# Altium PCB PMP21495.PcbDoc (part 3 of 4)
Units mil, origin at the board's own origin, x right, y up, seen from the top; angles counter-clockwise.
Board outline 10700 x 5800 mil, 6 copper layers (Top Layer, Signal Layer 3, Signal Layer 1, Signal Layer 2, Signal Layer 4, Bottom Layer), stack 66 mil thick; 305 components, 138 nets, 864 pads, 367 vias.
Unrouted connection lines stored in the file: 2.
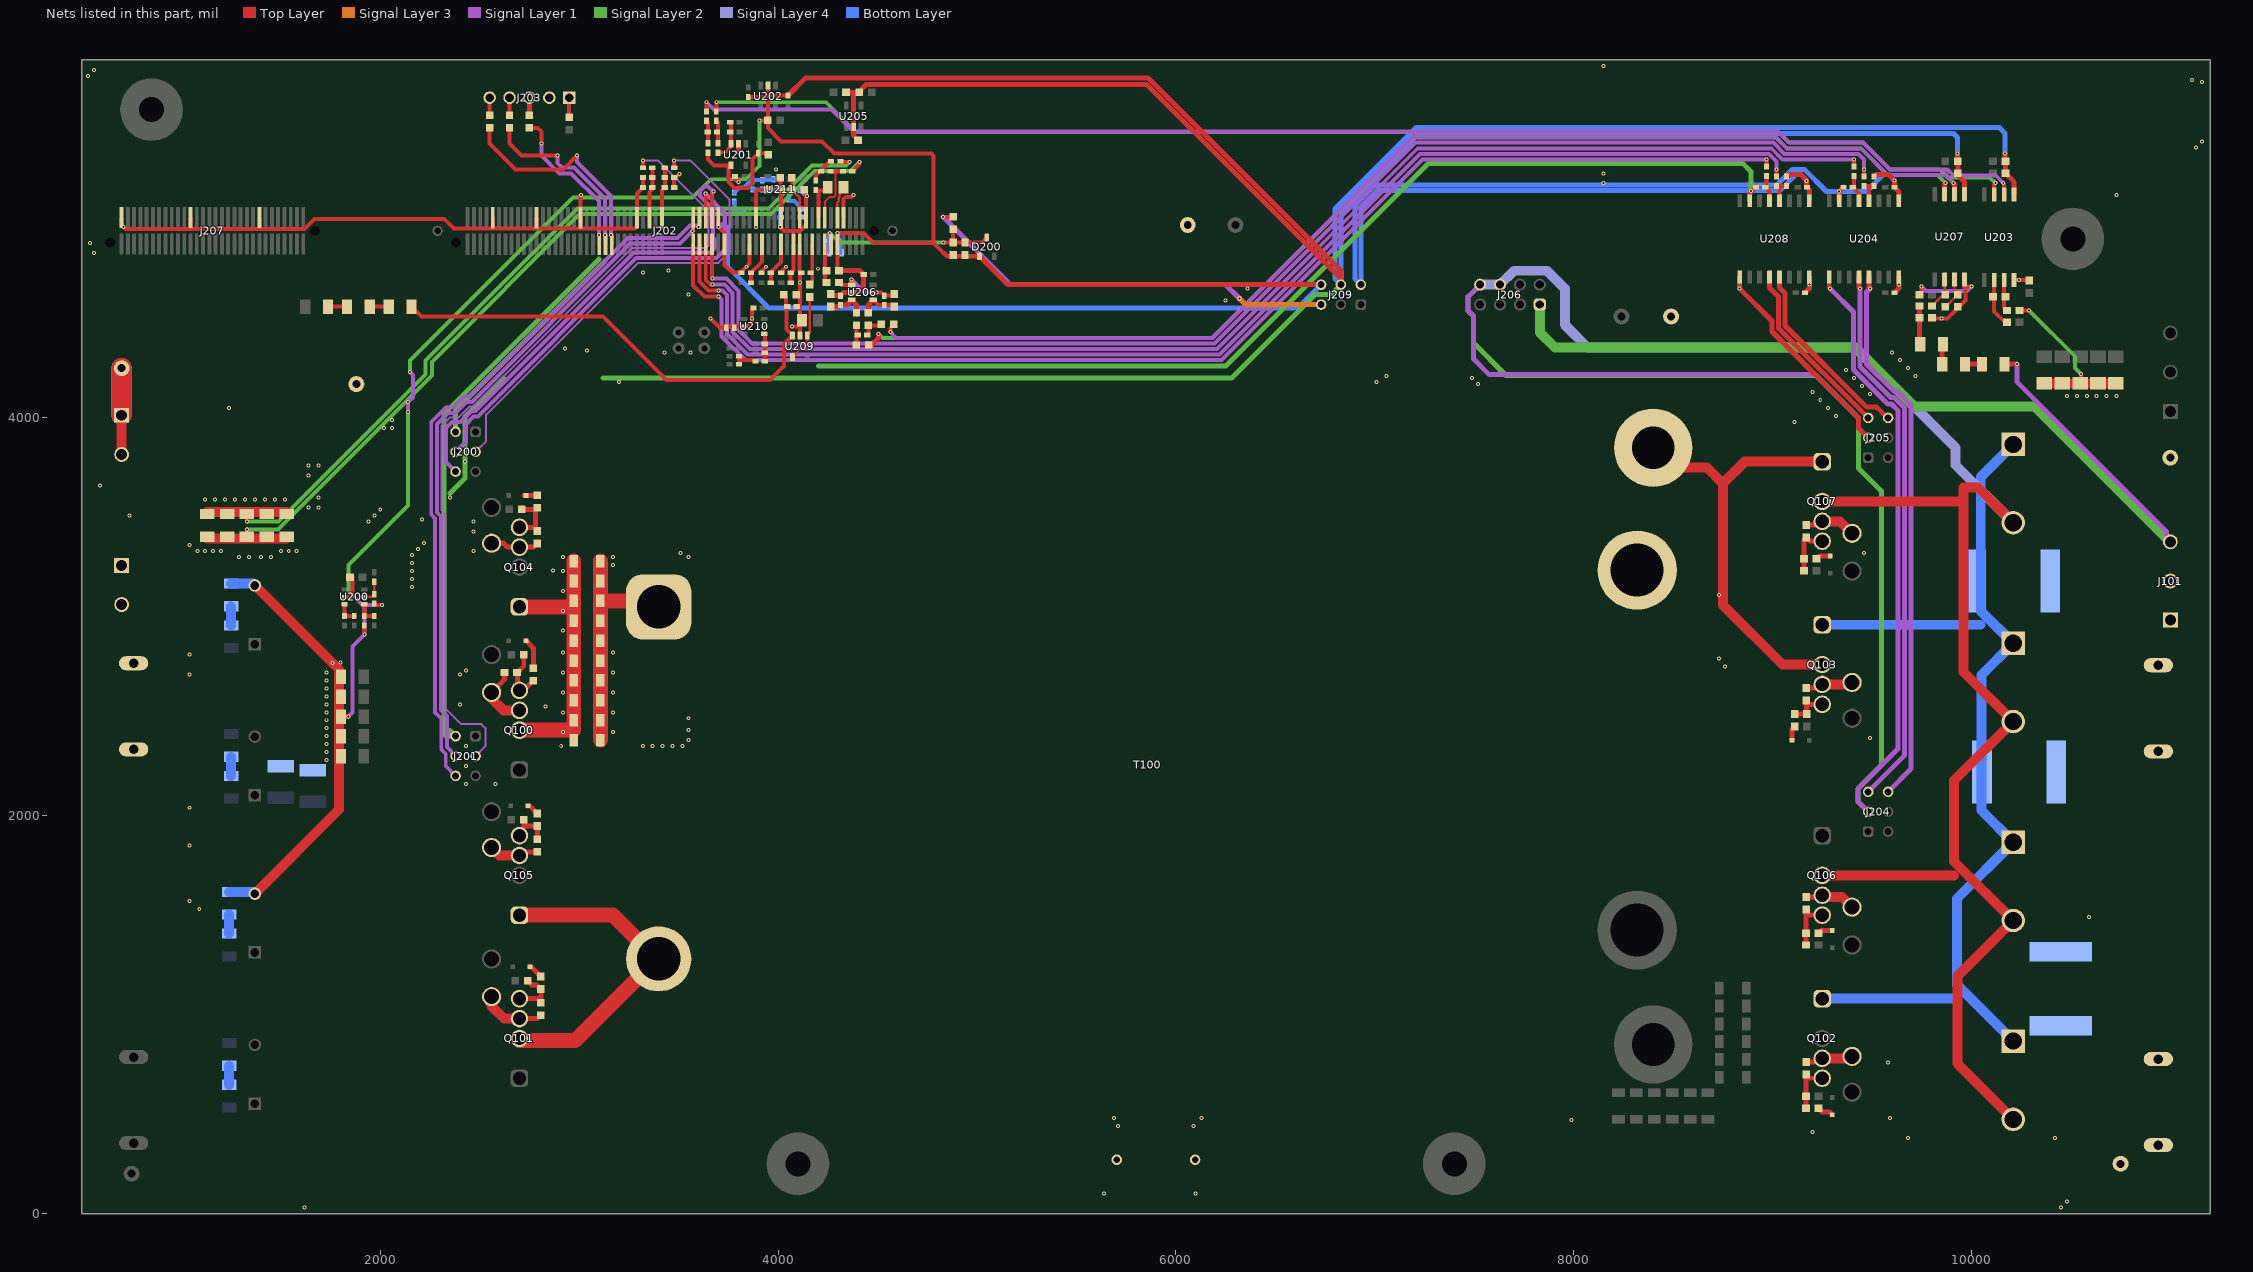
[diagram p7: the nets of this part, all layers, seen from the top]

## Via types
v1: diameter 20, hole 10, Top Layer to Bottom Layer, 367 vias

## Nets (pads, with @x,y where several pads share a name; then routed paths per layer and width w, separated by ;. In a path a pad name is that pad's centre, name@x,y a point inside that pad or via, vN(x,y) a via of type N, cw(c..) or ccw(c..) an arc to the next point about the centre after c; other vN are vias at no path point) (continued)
NetC103_1: C103.1 C104.1 C106.1 C107.1 C132.1 C133.1 C142.1 Q102.1 Q103.1 TP101.1 XF102.1 XF102.2 | length 4976
  Bottom Layer w50: Q102.1@9250,1080 9926.85,1080 ; Q103.1@9250,2960 10046.85,2960 ; C107.1@10210,866.85 9926.85,1150 9926.85,1583.7 C106.1@10210,1866.85 10050,2026.85 10050,2706.85 C104.1@10210,2866.85 10046.85,3030 10046.85,3703.7 C103.1@10210,3866.85
NetC122_1: C122.1 C124.1 C126.1 C128.1 C134.1 C136.1 C138.1 C140.1 C146.1 C148.1 T100.1 | length 1153.1
  Top Layer w75: C128.1@3106.93,2380 C134.1@3106.93,2480 C126.1@3106.93,2580 C122.1@3106.93,2680 C124.1@3106.93,2780 C146.1@3106.93,2880 C148.1@3106.93,2980 C140.1@3106.93,3080 ; C138.1@3106.93,3280 C136.1@3106.93,3180 C140.1@3106.93,3080 ; T100.1@3360,3080 C140.1@3106.93,3080
  other v1: 3320,2350 3370,2350 3420,2350 3470,2350 3520,2350 3550,2380 3170,2420 3550,2430 3550,2490 3170,2520 3170,2620 3170,2720 3170,2820 3170,3260 3170,3300 3550,3300 3510,3320
NetC122_2: C122.2 C124.2 C126.2 C128.2 C134.2 C136.2 C138.2 C140.2 C146.2 C148.2 Q100.2 Q104.1 | length 1346.1
  Top Layer w75: Q100.2@2710,2430 2973.07,2430 C134.2@2973.07,2480 C126.2@2973.07,2580 C122.2@2973.07,2680 C124.2@2973.07,2780 C146.2@2973.07,2880 C148.2@2973.07,2980 C140.2@2973.07,3080 C136.2@2973.07,3180 C138.2@2973.07,3280 ; Q104.1@2710,3050 2943.07,3050
  other v1: 2910,2350 2920,2420 2920,2520 2830,2550 2920,2620 2920,2720 2920,2820 2920,2930 2920,3030 2920,3130 2920,3230 2868.84,3232.2 2920,3300
NetC200_1: C200.1 R203.2 R211.1 | length 132.7
  Top Layer w20: R211.1@4190,5193.62 4190,5221.65 4258.35,5290 R203.2@4266.38,5290
NetC200_2: C200.2 J202.13 R207.2 | length 331.2
  Top Layer w10: J202.13@4235,5007.05 4235,5087.22 4257.78,5110 4279.55,5110 4290,5120.45 4290,5240
  Top Layer w20: C200.2@4263.62,5240 4290,5240 R207.2@4326.38,5240
NetC202_2: C202.2 J202.14 R209.1 | length 184.3
  Top Layer w20: R209.1@4235,4688.9 J202.14@4235,4873.19
NetC203_1: C203.1 R210.1 R214.2 U209.3 | length 2451.1
  Top Layer w20: R210.1@2157.09,4560 2207.09,4510 3120,4510 3440,4190 3960,4190 4030,4260 4030,4371.54 U209.3@4072.6,4414.13 4042.13,4444.61 4042.13,4564.25 4040,4566.38 4040,4608.5 R214.2@4028.5,4620
NetC204_1: C204.1 J202.21 R212.2 | length 217.7
  Top Layer w12: R212.2@4068.5,5207.13 C204.1@4068.5,5147.13 4110,5105.63 4110,5008.03 J202.21@4109.02,5007.05
NetC205_1: C205.1 J202.27 R218.1 | length 197
  Top Layer w12: C205.1@4008.5,5147.13 C205.1@4011.5,5147.13
  Top Layer w20: C205.1@4011.5,5150.12 R218.1@4011.5,5207.13 ; J202.27@4014.53,5007.05 C205.1@4014.53,5144.09
NetC206_1: C206.1 J202.57 R221.1 R223.2 | length 257.4
  Top Layer w19.68: J202.57@3416.1,5007.05 3416.1,5143.66
  Top Layer w20: 3416.1,5143.66 C206.1@3430.79,5158.35 R221.1@3430.79,5258.35
NetC207_1: C207.1 J202.61 R222.1 R224.2 | length 257.5
  Top Layer w19.68: J202.61@3353.11,5007.05 3353.11,5135.39
  Top Layer w20: 3353.11,5135.39 3368.03,5150.31 C207.1@3368.03,5158.35 R222.1@3368.03,5258.35
NetC208_2: C208.2 R225.1 R232.2 U201.4 | length 604
  Top Layer w20: R232.2@3648.35,5333.5 3648.35,5298.78 3678.87,5268.25 3761.67,5268.25 3750,5256.58 3750,5187.13 3780.37,5156.75 3812.58,5156.75 3812.96,5157.13 3850,5157.13 3871.81,5178.94 3871.81,5301.5 C208.2@3900.95,5330.64 R225.1@3950.95,5330.64
NetC215_1: C215.1 R230.2 U203.2 | length 245
  Top Layer w20: U203.2@10114.49,4693.46 10114.49,4535.51 10170,4480 R230.2@10178.5,4480
NetC215_2: C215.2 R235.2 U203.3 | length 159.3
  Top Layer w20: U203.3@10164.49,4693.46 10164.49,4554.02 R235.2@10178.5,4540
NetC216_1: C216.1 R231.2 R232.1 | length 116.2
  Top Layer w20: R231.2@3640,5493.5 3648.35,5485.16 R232.1@3648.35,5380.75
NetC216_2: C216.2 R233.2 R234.1 | length 116.2
  Top Layer w20: R233.2@3690,5493.5 3698.35,5485.16 R234.1@3698.35,5380.75
NetC217_1: C217.1 R234.2 R236.2 U201.3 | length 196.9
  Top Layer w19.68: R234.2@3698.35,5333.5 3733.5,5333.5 3763.54,5363.54 U201.3@3763.54,5378.39 C217.1@3763.54,5482.83
NetC221_2: C221.2 R238.1 R243.2 U206.4 | length 199.5
  Top Layer w20: U206.4@4478.54,4593.58 4504.76,4567.36 R238.1@4584.41,4567.36
  Top Layer w25: R243.2@4454.41,4520.85 4454.41,4569.45 U206.4@4478.54,4593.58
NetC228_1: C228.1 R241.2 U207.2 | length 161.1
  Top Layer w12: R241.2@9801.5,4562.8 9802.3,4562.8 9835.06,4595.55 9835.06,4596.36 9862.2,4623.5 9865,4623.5 U207.2@9865,4695.43
NetC228_2: C228.2 R247.2 U207.3 | length 170.1
  Top Layer w12: R247.2@9868.5,4560 9871.5,4560 C228.2@9931.5,4620 9915,4636.5 U207.3@9915,4695.43
NetC229_1: C229.1 R242.2 R243.1 | length 108
  Top Layer w20: C229.1@4454.41,4423.6 R243.1@4454.41,4465.73 4514.23,4465.73 R242.2@4518.5,4470
NetC229_2: C229.2 R244.2 R245.1 | length 100.5
  Top Layer w20: R244.2@4394.41,4373.11 R245.1@4394.41,4473.6
NetC232_1: C232.1 R245.2 R248.2 U206.3 | length 202.7
  Top Layer w25: R248.2@4264.41,4559.49 4306.54,4559.49 C232.1@4314.41,4567.36 4344.06,4567.36 U206.3@4370.28,4593.58 4394.41,4569.45 R245.2@4394.41,4520.85
NetC234_1: C234.1 R219.2 U204.5 | length 140.1
  Top Layer w20: R219.2@9410,5216.38 9410,5166.38 C234.1@9403.62,5160 9435,5128.62 U204.5@9435,5091.93
NetC235_1: C235.1 R200.2 U204.4 | length 124.4
  Top Layer w20: R200.2@9460,5166.38 C235.1@9510,5166.38 ; U204.4@9485,5091.93 9485,5166.38
NetC236_1: C236.1 R220.2 U208.5 | length 135.9
  Top Layer w20: R220.2@8970,5216.38 8970,5166.38 C236.1@8963.62,5160 8985,5138.62 U208.5@8985,5091.93
NetC237_1: C237.1 R201.2 U208.4 | length 119.4
  Top Layer w20: R201.2@9020,5166.38 C237.1@9070,5166.38 ; U208.4@9035,5091.93 9035,5161.38
NetC238_1: C238.1 C239.1 C240.1 D200.3 J202.12 R226.1 R227.2 | length 1040.9
  Top Layer w20: v1(4260,4930) 4266.5,4923.5 J202.12@4266.5,4873.19 ; v1(4831.5,4881.5) R227.2@4880,4881.5 ; R226.1@4880,4948.5 R227.2@4880,4881.5 ; D200.3@5050,4907.24 5024.25,4881.5 R227.2@4880,4881.5
  Signal Layer 2 w20: v1(4260,4930) 4308.5,4881.5 v1(4831.5,4881.5)
  Bottom Layer w20: C240.1@4256.38,4837.87 C239.1@4256.38,4890 4256.38,4926.38 v1(4260,4930)
NetC241_1: C241.1 J202.18 R228.1 | length 206.7
  Top Layer w20: R228.1@4160,4671.5 4172.01,4683.5 J202.18@4172.01,4873.19
NetC242_1: C242.1 J202.24 R229.2 | length 198.9
  Top Layer w20: R229.2@4063.62,4680 C242.1@4063.62,4730 4077.52,4743.9 J202.24@4077.52,4873.19
NetC244_1: C244.1 J202.34 R253.1 | length 217.2
  Top Layer w20: R253.1@3863.62,4680 C244.1@3863.62,4730 3864.1,4730 3882.76,4748.66 3882.76,4749.21 3893.23,4759.69 3893.78,4759.69 3920.04,4785.94 J202.34@3920.04,4873.19
NetC245_1: C245.1 J202.28 R254.1 | length 214.3
  Top Layer w20: R254.1@3963.62,4680 C245.1@3963.62,4730 3963.62,4733.62 4014.53,4784.53 J202.28@4014.53,4873.19
NetC246_2: C246.2 R255.1 R258.1 U210.4 | length 129.2
  Top Layer w20: R258.1@3933.62,4290 C246.2@3933.62,4327.72 U210.4@3933.62,4419.17
NetC248_1: C248.1 R257.2 R258.2 | length 122.8
  Top Layer w20: R257.2@3803.62,4270 3803.62,4290 ; C248.1@3803.62,4310 3803.62,4290 ; R258.2@3886.38,4290 3803.62,4290
NetC250_1: C250.1 R260.2 R264.2 U211.1 | length 294.1
  Bottom Layer w20: C250.1@3873.37,5148.27 4031.73,5148.27 4051.85,5128.15 U211.1@4051.85,5099.8 4061.65,5090 4082.01,5090 R264.2@4113.62,5058.38
NetC250_2: C250.2 R260.1 R263.1 U211.4 | length 216.8
  Bottom Layer w20: R263.1@3780,5133.62 3805.63,5159.25 3829.25,5159.25 C250.2@3865.51,5195.51 ; C250.2@3873.37,5195.51 3972.36,5195.51 U211.4@3977.05,5200.2
NetC252_1: C252.1 R262.2 R263.2 | length 102.8
  Bottom Layer w20: R263.2@3780,5086.38 R262.2@3780,5033.62 C252.1@3830,5033.62
NetD100_2: D100.2 R122.1 | length 153.7
  Top Layer w25: D100.2@2733.31,2880 2770,2843.31 R122.1@2770,2741.5
NetD101_2: D101.2 R123.1 | length 74
  Top Layer w25: D101.2@2753.31,1240 2758.68,1240 R123.1@2807.18,1191.5
NetD102_2: D102.2 R124.1 | length 82.2
  Top Layer w25: R124.1@9231.5,529.67 9251.16,510 9286.69,510 D102.2@9300,496.69
NetD103_2: D103.2 R125.1 | length 74
  Top Layer w25: D103.2@9098.05,2380 9098.05,2435.2 R125.1@9111.36,2448.5
NetD104_2: D104.2 R134.1 | length 65.2
  Top Layer w25: D104.2@2723.31,3610 R134.1@2788.5,3610
NetD105_2: D105.2 R135.1 | length 62.6
  Top Layer w25: D105.2@2743.31,2050 2751.5,2050 R135.1@2790,2011.5
NetD106_2: D106.2 R136.1 | length 74
  Top Layer w25: R136.1@9231.5,1410 9244.8,1423.31 D106.2@9300,1423.31
NetD107_2: D107.2 R137.1 | length 74.4
  Top Layer w25: R137.1@9221.5,3291.46 9235.83,3305.79 D107.2@9290,3305.79
NetJ105_1: J105.1 Q103.2 Q107.1 T100.8 | length 2163
  Top Layer w50: J105.1@8400,3750 8670,3750 8750,3670 ; Q103.2@9250,2760 9050,2760 8750,3060 8750,3670 ; Q107.1@9250,3780 8860,3780 8750,3670
  other v1: 8760,2750 8730,2790 8730,3110 9110,3980
NetJ202_15: J202.15 R206.1 R211.2 | length 166.5
  Top Layer w19.68: R211.2@4200,5143.5 R206.1@4233.5,5143.5 ; J202.15@4203.5,5007.05 4203.5,5140
NetJ203_1: J203.1 R252.1 | length 98.5
  Top Layer w20: R252.1@2950,5511.5 J203.1@2950,5610
NetJ203_3: J203.3 R249.2 | length 88.5
  Top Layer w25: R249.2@2750,5521.5 J203.3@2750,5610
NetJ203_4: J203.4 R251.2 | length 88.5
  Top Layer w20: R251.2@2650,5521.5 J203.4@2650,5610
NetJ203_5: J203.5 R250.2 | length 88.5
  Top Layer w20: R250.2@2550,5521.5 J203.5@2550,5610
NetJ204_5: J204.5 U204.12 | length 2768.6
  Top Layer w25: U204.12@9435,4708.07 9435,4655 v1(9440,4650)
  Signal Layer 1 w25: v1(9440,4650) 9440,4256.49 9593.62,4102.87 9612.02,4102.87 9662.87,4052.02 9662.87,2301.87 J204.5@9481,2120
NetJ204_6: J204.6 U204.13 | length 2747.9
  Top Layer w25: U204.13@9485,4708.07 9485,4655 v1(9490,4650)
  Signal Layer 1 w25: v1(9490,4650) 9472.87,4632.87 9472.87,4270.11 9607.23,4135.75 9625.64,4135.75 9695.75,4065.64 9695.75,2234.75 J204.6@9581,2120
NetJ205_5: J205.5 U208.12 | length 913.5
  Top Layer w25: U208.12@8985,4708.07 8985,4655 9030,4610 9030,4451 J205.5@9481,4000
NetJ205_6: J205.6 U208.13 | length 965.6
  Top Layer w25: U208.13@9035,4708.07 9035,4655 9062.87,4627.13 9062.87,4464.62 9473.73,4053.76 9523.73,4053.76 9577.49,4000 J205.6@9581,4000
NetQ100_4: Q100.4 R118.2 R122.2 R126.2 | length 287.3
  Top Layer w25: R118.2@2721.5,2810 2721.5,2751.5 2690,2720 2690,2640 Q100.4@2700,2630 2721.5,2630 R122.2@2770,2678.5
NetQ101_2: Q101.2 Q105.1 T100.3 | length 1641
  Top Layer w75: Q101.2@2700,870 2980,870 3390,1280 3170,1500 Q105.1@2700,1500
NetQ101_4: Q101.4 R119.2 R123.2 R127.2 | length 238.6
  Top Layer w25: Q101.4@2700,1080 2807.18,1080 R123.2@2807.18,1128.5 2785.69,1150 2761.5,1150 R119.2@2741.5,1170
NetQ102_4: Q102.4 R120.2 R124.2 R128.2 | length 239.5
  Top Layer w25: R124.2@9168.5,529.67 R120.2@9168.5,589.67 9168.5,697.01 R128.2@9170,698.5 ; R128.2@9179.98,680 Q102.4@9250,680
NetQ103_4: Q103.4 R121.2 R125.2 R129.2 | length 197.6
  Top Layer w25: R125.2@9111.36,2511.5 R121.2@9171.36,2511.5 9170,2512.85 R129.2@9170,2578.5 ; R129.2@9179.98,2560 Q103.4@9250,2560
NetQ104_4: Q104.4 R130.2 R134.2 R138.2 | length 241.5
  Top Layer w25: Q104.4@2700,3450 R138.2@2771.5,3450 ; R130.2@2711.5,3540 2781.5,3540 R138.2@2781.5,3440
NetQ105_4: Q105.4 R131.2 R135.2 R139.2 | length 190.9
  Top Layer w25: Q105.4@2721.5,1921.5 R131.2@2721.5,1980 ; 2722.99,1948.5 R135.2@2790,1948.5 R139.2@2790,1883.11
NetQ106_4: Q106.4 R132.2 R136.2 R140.2 | length 257.5
  Top Layer w25: R132.2@9168.5,1350 R136.2@9168.5,1410 R140.2@9168.5,1527.01 ; 9169.53,1500 Q106.4@9250,1500
NetQ107_4: Q107.4 R133.2 R137.2 R141.2 | length 259.5
  Top Layer w25: R133.2@9158.5,3231.46 R137.2@9158.5,3291.46 9158.5,3387.01 R141.2@9170,3398.5 9188.5,3380 Q107.4@9250,3380
NetR100_1: R100.1 R105.2 | length 95.8
  Bottom Layer w50: R100.1@1240,647.09 R105.2@1240,742.91
NetR101_1: R101.1 R106.2 | length 95.8
  Bottom Layer w50: R101.1@1250,2200.18 R106.2@1250,2296
NetR110_1: R110.1 R114.2 | length 95.8
  Bottom Layer w50: R110.1@1240,1407.09 R114.2@1240,1502.91
NetR111_1: R111.1 R115.2 | length 95.8
  Bottom Layer w50: R111.1@1250,2957.09 R115.2@1250,3052.91
NetR202_1: R202.1 R205.2 | length 95.8
  Top Layer w20: R202.1@1737.09,4560 R205.2@1832.91,4560
NetR204_1: R204.1 R216.2 U200.4 | length 108.8
  Top Layer w20: R216.2@1920,3003.62 R204.1@1970,3003.62 ; R216.2@1920.2,3003.82 U200.4@1920.2,3062.6
NetR205_1: R205.1 R210.2 | length 95.8
  Top Layer w20: R205.1@1947.09,4560 R210.2@2042.91,4560
NetR208_1: R208.1 R217.2 U200.5 | length 118.2
  Top Layer w12: U200.5@1920.2,3100 1956.38,3100 R217.2@1970,3113.62 R208.1@1970,3176.38
NetR213_1: R213.1 R215.2 U200.3 | length 108.8
  Top Layer w20: U200.3@1819.8,3062.6 1819.8,3003.82 R215.2@1869.8,3003.82
NetR231_1: R231.1 U203.6 | length 6794.3
  Top Layer w20: R231.1@3640,5540.75 v1(3640,5587.13) ; v1(10160,5180) 10164.49,5175.51 U203.6@10164.49,5122.6
  Signal Layer 1 w20: v1(3640,5587.13) 3677.13,5550 4269.37,5550 4380,5439.37 9028.31,5439.37 9084.06,5383.62 9455.22,5383.62 9590.22,5248.62 9880.8,5248.62 9909.42,5220 10120,5220 v1(10160,5180)
NetR233_1: R233.1 U203.7 | length 6704.7
  Top Layer w20: R233.1@3690,5540.75 v1(3690,5587.13) ; U203.7@10114.49,5122.6 10114.49,5174.49 v1(10120,5180)
  Signal Layer 2 w20: v1(3690,5587.13) 4240.75,5587.13 4390,5437.87 9029.8,5437.87 9083.84,5383.84 9455,5383.84 9590.22,5248.62 9840.8,5248.62 9879.71,5209.71 10090.29,5209.71 v1(10120,5180)
NetR237_1: R237.1 R239.2 | length 85.8
  Top Layer w25: R239.2@9967.09,4270 R237.1@10052.91,4270
NetR239_1: R239.1 R240.2 | length 95.8
  Top Layer w25: R239.1@9852.91,4270 R240.2@9852.91,4365.83
NetR240_1: R240.1 R241.1 R246.2 | length 171.3
  Top Layer w25: R240.1@9738.5,4374.41 R246.2@9738.5,4502.8 R241.1@9738.5,4545.71
NetR242_1: R242.1 U207.6 | length 5975.4
  Top Layer w20: v1(4564.41,4430.98) 4564.41,4452.91 R242.1@4581.5,4470
  Top Layer w25: v1(9910,5180) 9915,5175 U207.6@9915,5124.57
  Signal Layer 1 w20: v1(4564.41,4430.98) 4593.58,4401.81 6183.55,4401.81 7193.24,5411.5 9016.76,5411.5 9072.51,5355.75 9443.67,5355.75 9578.68,5220.74 9869.26,5220.74 v1(9910,5180)
NetR244_1: R244.1 U207.7 | length 6035.2
  Top Layer w25: R244.1@4448.03,4366.73 4470.16,4366.73 4504.41,4400.98 v1(4504.41,4420.98) ; U207.7@9865,5124.57 9865,5175 v1(9870,5180)
  Signal Layer 2 w20: v1(4504.41,4420.98) 4524.41,4400.98 6182.53,4400.98 7191.55,5410 9018.26,5410 9072.51,5355.75 9443.67,5355.75 9578.68,5220.74 9829.26,5220.74 v1(9870,5180)
PGND: C111.2 C112.2 C130.2 C131.2 C158.2 C201.2 C202.1 C203.2 C204.2 C205.2 C206.2 C207.2 C210.2 C211.2 C212.2 C213.2 C218.1 C219.2 C220.2 C222.2 C224.2 C225.2 C226.2 C227.2 C230.2 C231.2 C232.2 C234.2 C235.2 C236.2 C237.2 C238.2 C239.2 C240.2 C241.2 C242.2 C243.2 C244.2 C245.2 C247.2 C249.2 C251.2 C253.2 C254.2 D200.1 J200.2 J201.2 J202.7 J202.10 J202.19 J202.22 J202.35 J202.38 J202.46 J202.47 J202.65 J202.83 J202.97 J202.111 J203.2 J207.135 J207.157 J207.179 J209.2 J209.4 J209.6 R103.1 R107.1 R109.1 R113.1 R114.1 R115.1 R117.1 R142.1 R143.1 R144.1 R145.1 R146.1 R207.1 R214.1 R216.1 R217.1 R223.1 R224.1 R227.1 R248.1 R259.1 R265.1 TP106.1 TP107.1 U200.2 U201.2 U202.2 U203.5 U204.1 U204.7 U205.2 U206.2 U207.5 U208.1 U208.7 U209.2 U210.2 U211.2 | length 60595.8
  Top Layer w19.68: 1392.48,4952.48 J207.135@1392.48,5007.91
  Top Layer w20: J207.179@699.57,4970.43 J207.179@699.57,5007.91 ; 720,4950 1620,4950 1670,5000 2321.81,5000 2370,4951.81 3281.81,4951.81 J202.65@3290,4960 ; J207.157@1046.02,4956.02 J207.157@1046.02,5007.91 ; R109.1@1330,3393.07 R109.1@1330,3402.91 v1(1330,3440) ; R144.1@1794.41,2500 v1(1840,2500) ; U200.2@1819.8,3100 1850,3100 v1(1860,3110) C201.2@1860,3200 ; v1(1920,2910) R216.1@1920,2956.38 ; R217.1@1970,3066.38 1976.38,3060 v1(2010,3060) ; J202.111@2565.71,4956.11 J202.111@2565.71,5007.05 ; J202.97@2786.18,4955.63 J202.97@2786.18,5007.05 ; J202.83@3006.65,4955.16 J202.83@3006.65,5007.05 3006.65,5116.65 v1(3010,5120) ; J202.65@3290.12,4960.12 J202.65@3290.12,5007.05 3290.12,5127.68 C207.2@3320.79,5158.35 R224.1@3320.79,5208.35 ; C206.2@3478.03,5158.35 R223.1@3478.03,5208.35 3484.61,5208.35 v1(3503.62,5227.36) ; v1(3660,4500) 3706.38,4453.62 R259.1@3740,4453.62 ; J202.47@3699.57,5007.05 3699.57,4960.43 v1(3700,4960) 3731.06,4928.94 J202.46@3731.06,4873.19 3731.06,4768.94 3770,4730 C244.2@3816.38,4730 3816.38,4735.59 v1(3840.79,4760) 3857.05,4776.26 J202.38@3857.05,4873.19 ; R259.1@3746.38,4460 U210.2@3829.8,4460 3850,4460 3870,4480 v1(3870,4500) C247.2@3870,4546.5 ; C222.2@3850,5613.5 3946.38,5613.5 ; v1(3890,4960) 3888.54,4961.46 J202.35@3888.54,5007.05 3888.54,5135.67 3900,5147.13 C205.2@3948.5,5147.13 ; v1(3905.59,5496.14) C218.1@3947.52,5496.14 ; C245.2@3916.38,4730 3920,4733.62 3920,4740 v1(3940,4760) ; C218.1@3948.5,5497.13 3948.5,5457.83 4015.59,5390.75 4221.57,5390.75 4284.04,5328.27 4772.31,5328.27 4782.76,5317.82 4782.76,4880 ; C218.1@3950,5498.62 U202.2@3950,5671.26 ; 3953.62,5620.75 C220.2@4050,5620.75 ; v1(4010,4960) 4030,4940 4110,4940 4140.51,4970.51 J202.19@4140.51,5007.05 4140.51,5138.11 C204.2@4131.5,5147.13 ; C242.2@4016.38,4730 4016.38,4736.38 v1(4040,4760) ; v1(4070,4460) 4110,4460 U209.2@4110,4414.13 ; C241.2@4109.02,4737.36 J202.22@4109.02,4873.19 ; C243.2@4110,4504.13 C241.2@4110,4723.62 ; C202.1@4297.99,4748.9 J202.10@4297.99,4873.19 v1@4297.99,4927.99 ; v1(4300,4930) 4430,4930 4480,4880 4782.76,4880 ; J202.7@4329.49,5007.05 4329.49,5099.49 4340.63,5110.63 4370.63,5110.63 v1(4380,5120) ; R207.1@4373.62,5240 4410,5276.38 v1(4410,5287.13) ; 4832.76,4830 4782.76,4880
  Top Layer w25: C212.2@3783.7,5214.26 3783.7,5203.42 v1(3800,5187.13) ; v1(3800.95,5334.1) U201.2@3800.95,5378.39 ; C220.2@4050,5620.75 4139.25,5710 5860,5710 6830,4740 6830,4700.26 ; R248.1@4264.41,4614.6 C232.2@4314.41,4614.61 4330.79,4630.98 U206.2@4370.28,4630.98 4404.41,4630.98 4430.79,4657.36 C226.2@4430.79,4720.98 4410.79,4740.98 C202.1@4305.91,4740.98 ; C230.2@4341.5,5637.13 C227.2@4408.5,5637.13 4408.5,5641.33 4443.37,5676.2 5854.06,5676.2 6830,4700.26 ; 4380,5637.11 U205.2@4380,5462.99 4380,5418.62 C231.2@4401.5,5397.13 ; 4832.76,4830 4850,4812.76 D200.1@5012.6,4812.76 5155.35,4670 J209.6@6730,4670 ; J209.4@6830,4670 6830,4700.26 ; U208.7@8885,5091.93 8885,5128.62 ; v1@8893.58,5137.2 C236.2@8916.38,5160 ; C237.2@9070,5213.62 9079.25,5222.87 9143.62,5222.87 9170,5196.49 v1(9170,5190) 9170,5163.62 C213.2@9173.62,5160 9185,5148.62 U208.1@9185,5091.93 ; U204.7@9335,5091.93 v1(9335,5138.62) C234.2@9356.38,5160 ; C235.2@9510,5213.62 9519.25,5222.87 9583.62,5222.87 v1(9613.62,5192.87) C219.2@9613.62,5160 9635,5138.62 U204.1@9635,5091.93 ; C224.2@9930,5291.5 v1(9930,5330) ; C224.2@9931.5,5290 C225.2@9931.5,5230 9931.5,5221.3 9965,5187.8 U207.5@9965,5124.57 ; C210.2@10170,5291.5 v1(10170,5330) ; C210.2@10171.5,5290 C211.2@10171.5,5230 10214.49,5187.01 U203.5@10214.49,5122.6
  Top Layer w50: R107.1@1130,3393.07 1330,3393.07 R113.1@1530,3393.07 ; C111.2@1370,1607.64 1793.07,2030.71 1793.07,2734.57 C112.2@1370,3157.64
  Signal Layer 1 w20: 1330,3421.46 v1(1330,3440) ; 1817.2,2500 v1(1840,2500) 1860,2520 1860,2850 v1(1920,2910) 1920,3059.8 ; v1(1860,3110) 1910,3060 v1(2010,3060) ; v1(2140,4030) v1(2140,4080) 2163.62,4103.62 2163.62,4216.38 v1(2150,4230)
  Signal Layer 2 w20: v1(1330,3440) 1486.89,3440 2259.71,4212.82 2259.71,4281.22 3002.74,5024.25 3964.83,5024.25 4182.71,5242.13 4365,5242.13 v1(4410,5287.13) ; 1817.2,2500 v1(1840,2500) ; v1(1860,3110) 1840,3130 1840,3260 2140,3560 v1(2140,4030) ; v1(2150,4230) 2150,4289.77 2968.1,5107.87 3570,5107.87 3662.13,5200 3840,5200 3905.59,5265.59 v1(3905.59,5496.14)
  Signal Layer 2 w25: 2349.63,3619.63 2425.95,3695.95 2425.95,4004.05 2425,4005 2620,4200 ; 2350,2421 2350,2429 J201.2@2379,2400 2329,2400 2320,2409 2320,4018.26 3100,4798.26 ; J200.2@2379,3930 2379,4037.84 3129.63,4788.47 ; 3120,4200 6280,4200 6700,4620 6780,4620 J209.4@6830,4670 ; 4204.41,4260.98 6250.98,4260.98 7270,5280 8850,5280 8890.79,5239.21 v1(8890.79,5140)
  Signal Layer 3 w20: 1330,3421.46 v1(1330,3440) ; 1817.2,2500 v1(1840,2500)
  Signal Layer 4 w20: 1330,3421.46 v1(1330,3440) ; 1817.2,2500 v1(1840,2500)
  Bottom Layer w20: 1330,3421.46 v1(1330,3440) ; 1817.2,2500 v1(1840,2500) ; v1(4010,4960) 4010,5025.07 ; C251.2@4110,5146.38 4140.23,5116.14 v1(4146.1,5116.14) ; v1(4300,4930) 4303.62,4926.38 C239.2@4303.62,4890 ; C240.2@4311.5,4830 C239.2@4311.5,4882.13
  Bottom Layer w25: 3700,4970 3730,4970 3746.49,4953.51 3746.49,4760 3953.62,4552.87 6612.87,4552.87 J209.6@6730,4670 ; 4013.62,5025.07 U211.2@4013.62,5098.98 ; v1(9170,5190) 9170,5196.49 9143.62,5222.87 9116.38,5222.87 9036.38,5142.87 7016.38,5142.87 6930,5056.49 J209.2@6930,4670 6900,4700 6900,5070 7000,5170 9020,5170 9100,5250 9160,5250 9271.38,5138.62 v1(9335,5138.62) 9472.13,5138.62 9556.38,5222.87 9583.62,5222.87 v1(9613.62,5192.87) ; v1(9930,5330) 9930,5410 9910,5430 7220,5430 6830,5040 J209.4@6830,4670 6800,4700 6800,5050 7210,5460 10140,5460 10170,5430 v1(10170,5330)
  Bottom Layer w50: R114.1@1240,1617.09 1360.55,1617.09 C111.2@1370,1607.64 ; R115.1@1250,3167.09 1360.55,3167.09 C112.2@1370,3157.64
  other v1: 1620,30 5640,100 5710,440 5690,480 1090,1530 1040,1570 1040,1850 1040,2040 2430,2160 2580,2160 2430,2250 1730,2280 1730,2320 2430,2350 1730,2360 1730,2400 1730,2440 1730,2480 1730,2520 1730,2560 2400,2560 1730,2600 1730,2640 1730,2680 1040,2710 2400,2710 1730,2720 2430,2730 1760,2767.64 1800,2770 1040,2810 2160,3150 2160,3190 2160,3230 2160,3270 1290,3300 1340,3300 1400,3300 1450,3300 2160,3310 1080,3330 1120,3330 1160,3330 1200,3330 1500,3330 1540,3330 1580,3330 2470,3330 2190,3340 1040,3360 2220,3370 2470,3430 1940,3480 2470,3480 2210,3490 1970,3510 2000,3540 1640,3550 1690,3550 1690,3600 2350,3600 1640,3710 1640,3760 1690,3760 2425.95,3780 2020,3950 2060,3950 2060,3990 3200,4180 7010,4180 7060,4210 3430,4330 3560,4330 3040.58,4340 2930,4350 6250,4590 3550,4620 6360,4650 4110,4680 3320,4730 3450,4740 4200,4750 560,4830 540,4880 709.78,4960.22 10730,5120 8150,5180 8150,5230 3990,5250 11130,5360 11160,5390 11160,5690 11110,5700 530,5720 560,5750 8150,5770
PRI_FAULT: J202.74 R250.1 | length 1120.3
  Top Layer w20: R250.1@2550,5458.5 2550,5380 2680,5250 2920,5250 v1(2990,5320) ; v1(3160,4920) 3164.13,4915.87 J202.74@3164.13,4873.19
  Signal Layer 1 w20: v1(2990,5320) 2990,5285.59 3160,5115.59 v1(3160,4920)
PWM1A: J200.6 J202.49 | length 2506.2
  Top Layer w20: J202.49@3668.07,5007.05 3668.07,5132.01 v1(3674.41,5138.35)
  Signal Layer 1 w20: J200.6@2379,3730 2330,3779 2330,3949.42 2360.58,3980 2403.37,3980 2458.45,4035.08 2479.4,4035.08 3275.07,4830.75 3660,4830.75 3680,4850.75 3680,4900.58 3672.13,4908.45 3672.13,5051.21 3606.54,5116.8 3606.54,5141.09 3630,5164.55 3648.2,5164.55 v1(3674.41,5138.35)
PWM1B: J200.4 J202.51 | length 2272.1
  Top Layer w20: v1(3634.41,5128.35) 3636.57,5126.18 J202.51@3636.57,5007.05
  Signal Layer 1 w20: J200.4@2379,3830 2430,3881 2430,3967.21 2470,4007.21 2490.95,4007.21 3286.61,4802.87 3690.53,4802.87 3734.25,4846.6 3734.25,5028.5 v1(3634.41,5128.35)
PWM2A: J201.6 J202.53 | length 3636
  Top Layer w20: v1(3600,4960) 3605.08,4965.08 J202.53@3605.08,5007.05
  Signal Layer 1 w20: J201.6@2379,2200 2329.37,2249.63 2329.37,2310.21 2306.68,2332.9 2306.68,2488.63 2276.38,2518.92 2276.38,3493.98 2256.38,3513.98 2256.38,3979.91 2330.09,4053.62 2367.45,4053.62 2422.54,4108.7 2448.91,4108.7 3244.57,4904.37 3494.95,4904.37 3558.45,4967.87 3592.13,4967.87 v1(3600,4960)
PWM2B: J201.4 J202.55 | length 3464.4
  Top Layer w20: v1(3570,4940) 3572.13,4942.13 3572.13,5005.59 J202.55@3573.58,5007.05
  Signal Layer 1 w20: J201.4@2379,2300 2334.55,2344.45 2334.55,2500.17 2304.25,2530.47 2304.25,3505.53 2284.25,3525.53 2284.25,3968.37 2341.63,4025.75 2379,4025.75 2434.08,4080.83 2460.45,4080.83 3256.12,4876.5 3506.5,4876.5 v1(3570,4940)
PWM3A: J202.50 R200.1 | length 6750.4
  Top Layer w20: v1@3668.07,4701.93 J202.50@3668.07,4873.19 ; R200.1@9460,5213.62 v1(9460,5250)
  Signal Layer 1 w20: v1(3670,4700) 3740,4700 3801.65,4638.35 3801.65,4442.28 3870,4373.94 6195.1,4373.94 7204.78,5383.62 9005.22,5383.62 9060.97,5327.87 9432.13,5327.87 9460,5300 v1(9460,5250)
PWM3B: J202.52 R219.1 | length 6689.6
  Top Layer w20: J202.52@3636.57,4873.19 3636.57,4694.01 3660.58,4670 v1(3670,4670) ; R219.1@9410,5263.62 v1(9410,5300)
  Signal Layer 1 w20: v1(3670,4670) 3730.58,4670 3771.39,4629.19 3771.39,4433.12 3858.45,4346.06 6207.22,4346.06 6209.33,4348.17 6209.33,4348.75 7216.33,5355.75 8993.67,5355.75 9049.42,5300 v1(9410,5300)
PWM4A: J202.54 R201.1 | length 6412.6
  Top Layer w20: J202.54@3605.08,4873.19 3605.08,4684.92 3650,4640 v1(3700,4640) ; R201.1@9020,5213.62 v1(9020,5250)
  Signal Layer 1 w20: v1(3700,4640) 3721.16,4640 3743.52,4617.64 3743.52,4421.58 3846.91,4318.19 6218.77,4318.19 6260.29,4359.71 ; 6237.2,4337.2 7227.87,5327.87 8982.13,5327.87 9020,5290 v1(9020,5250)
PWM4B: J202.56 R220.1 | length 6321.6
  Top Layer w20: J202.56@3573.58,4873.19 3573.58,4666.42 3630,4610 v1(3700,4610) ; R220.1@8970,5263.62 v1(8970,5300)
  Signal Layer 1 w20: v1(3700,4610) 3715.65,4594.35 3715.65,4410.03 3835.36,4290.31 6230.31,4290.31 7240,5300 v1(8970,5300)
RSVD1_P: J200.3 R221.2 | length 2430.4
  Top Layer w20: R221.2@3478.03,5258.35 v1(3478.03,5294.72)
  Signal Layer 1 w10: J200.3@2479,3830 2532.13,3883.13 2532.13,4016.04 3296.09,4780 3700,4780 3757.13,4837.13 3757.13,5096.96 3559.37,5294.72 v1(3478.03,5294.72)
RSVD2_P: J201.3 R222.2 | length 4194.4
  Top Layer w20: R222.2@3320.79,5258.35 v1(3320.79,5294.72)
  Signal Layer 1 w10: J201.3@2479,2300 2528.58,2349.58 2528.58,2440 2508.58,2460 2407.07,2460 2327.13,2539.95 2327.13,3515 2307.13,3535 2307.13,3958.89 2351.11,4002.87 2393.9,4002.87 2448.98,4057.96 2469.93,4057.96 3265.59,4853.62 3637.74,4853.62 3649.25,4865.14 3649.25,5041.74 3396.26,5294.72 v1(3320.79,5294.72)
RTN: J103.1 J103.2 R103.2 R107.2 R109.2 R113.2 R117.2 R203.1 TP103.1 | length 5006.6
  Top Layer w20: v1(1330,3480) R109.2@1330,3517.09 R109.2@1330,3526.93 ; R203.1@4313.62,5290 4316.5,5287.13 v1(4360,5287.13)
  Top Layer w50: J103.2@700,3816.54 J103.1@700,4013.39 ; R107.2@1130,3526.93 1330,3526.93 R113.2@1530,3526.93
  Top Layer w100: J103.1@700,4013.39 TP103.1@700,4250
  Signal Layer 2 w20: v1(1330,3480) 1487.47,3480 2226.9,4219.43 2226.9,4287.83 2991.19,5052.13 3953.29,5052.13 4171.16,5270 4342.87,5270 v1(4360,5287.13)
  Bottom Layer w20: v1(1330,3480) 1330,3503.46
  Bottom Layer w100: J103.1@700,4013.39 TP103.1@700,4250
  other v1: 740,3510 1120,3590 1170,3590 1220,3590 1270,3590 1320,3590 1370,3590 1420,3590 1470,3590 1520,3590 590,3660 1240,4050
S1H_P: Q100.3 R126.1 TP206.1 | length 321.4
  Top Layer w25: TP206.1@2560,2620 2624.05,2684.06 R126.1@2624.05,2720
  Top Layer w50: TP206.1@2560,2620 2560,2590 2620,2530 Q100.3@2700,2530
S1H_S: Q102.3 R128.1 TP214.1 | length 245.9
  Top Layer w25: R128.1@9170,761.5 9231.5,761.5 Q102.3@9250,780
  Top Layer w50: Q102.3@9250,780 9380,780 TP214.1@9400,800
S1L_P: Q104.3 R138.1 TP202.1 | length 245.9
  Top Layer w25: TP202.1@2560,3370 2620,3370 2640,3350 Q104.3@2700,3350 2771.5,3350 R138.1@2790,3368.5
S1L_S: Q106.3 R140.1 TP210.1 | length 251.3
  Top Layer w25: R140.1@9170,1591.5 Q106.3@9241.5,1591.5
  Top Layer w50: Q106.3@9241.5,1591.5 9348.5,1591.5 TP210.1@9400,1540
S2H_P: Q101.3 R127.1 TP207.1 | length 327.5
  Top Layer w25: Q101.3@2700,980 2790.67,980 R127.1@2807.09,996.41
  Top Layer w50: TP207.1@2560,1090 2560,1042.07 2622.07,980 Q101.3@2700,980
S2H_S: Q103.3 R129.1 TP215.1 | length 219.8
  Top Layer w25: R129.1@9170,2641.5 Q103.3@9231.5,2641.5
  Top Layer w50: Q103.3@9250,2660 9380,2660 TP215.1@9400,2680
S2L_P: Q105.3 R139.1 TP203.1 | length 226.5
  Top Layer w25: Q105.3@2718.5,1818.5 R139.1@2788.39,1818.5
  Top Layer w50: TP203.1@2560,1840 2600,1800 Q105.3@2700,1800
S2L_S: Q107.3 R141.1 TP211.1 | length 262.5
  Top Layer w25: R141.1@9170,3461.5 9231.5,3461.5 Q107.3@9250,3480
  Top Layer w50: Q107.3@9250,3480 9340,3480 TP211.1@9400,3420
SCI_RX0: J202.76 R251.1 | length 925.8
  Top Layer w20: R251.1@2650,5458.5 2650,5380 2710,5320 v1(2890,5320) ; v1(3130,4920) 3132.13,4917.87 3132.13,4873.7 J202.76@3132.64,4873.19
  Signal Layer 1 w20: v1(2890,5320) 2890,5282.79 2914.92,5257.87 2974.92,5257.87 3130,5102.79 v1(3130,4920)
SCI_TX0: J202.78 R249.1 | length 790.2
  Top Layer w20: R249.1@2750,5458.5 2791.5,5458.5 2810,5440 v1(2810,5380) ; v1(3100,4920) 3101.14,4918.86 J202.78@3101.14,4873.19
  Signal Layer 1 w20: v1(2810,5380) 2810,5320 2900,5230 2960,5230 3100,5090 v1(3100,4920)
SGND: C103.2 C104.2 C106.2 C107.2 C132.2 C133.2 C142.2 C158.1 C209.1 C214.2 C223.1 C233.2 J204.3 J205.3 J206.6 J206.8 Q106.2 Q107.2 R102.2 R104.2 R108.2 R112.2 R116.2 R235.1 R246.1 R247.1 TP102.1 TP105.1 U203.4 U204.9 U204.16 U207.4 U208.9 U208.16 | length 21875.7
  Top Layer w20: U204.9@9285,4708.07 9285,4655 v1(9290,4650) ; C223.1@9738.5,4620 9750,4631.5 v1(9750,4660) ; R246.1@9804.3,4500 v1(9850,4500) 9880,4500 9931.5,4551.5 9931.5,4552.8 9932.79,4552.8 9970,4590.01 9970,4650 9965,4655 U207.4@9965,4695.43 ; 9970,4660 v1(10000,4660) ; U203.4@10214.49,4693.46 C209.1@10288.03,4693.46 ; R235.1@10241.5,4540 v1(10290,4540) ; R112.2@10550,4177.32 v1(10550,4220)
  Top Layer w25: U208.9@8835,4708.07 v1(8835,4649.51) 8997.13,4487.38 8997.13,4434.29 9431.42,4000 9431.42,3949.58 J205.3@9481,3900 ; C233.2@9163.62,4630 9185,4651.38 U208.16@9185,4708.07 ; C214.2@9613.62,4630 9635,4651.38 U204.16@9635,4708.07
  Top Layer w50: Q106.2@9250,1700 9913.15,1700 ; Q107.2@9250,3580 9960,3580 ; C107.2@10210,473.15 9930,753.15 9930,1193.15 C106.2@10210,1473.15 9913.15,1770 9913.15,2176.3 C104.2@10210,2473.15 9960,2723.15 9960,3580 ; C103.2@10210,3473.15 10033.15,3650 9960,3650 9960,3580 ; R102.2@10366.4,4173.72 R112.2@10546.4,4173.72 R108.2@10636.4,4173.72 R104.2@10726.4,4173.72
  Signal Layer 1 w20: v1(9750,4660) 9771.3,4638.7 9978.7,4638.7 v1(10000,4660) ; 10550,4190 v1(10550,4220)
  Signal Layer 1 w25: J206.8@7530,4670 7470,4610 7470,4540 7497.13,4512.87 7497.13,4296.38 7576.38,4217.13 9214.29,4217.13 9431.42,4000 9431.42,3949.58 J205.3@9481,3900 ; v1(9290,4650) 9407.13,4532.87 9407.13,4242.87 9580,4070 9598.4,4070 9630,4038.4 9630,2335.4 9430,2135.4 9430,2071 J204.3@9481,2020
  Signal Layer 2 w20: v1(10290,4540) 10520,4310 10520,4250 v1(10550,4220) 10550,4200
  Signal Layer 2 w25: J206.8@7530,4670 7470,4610 7470,4537.13 7497.13,4510 7497.13,4376.38 7660,4213.51 9220,4213.51 9431.42,4002.09 9431.42,3748.58 9547.13,3632.87 9547.13,2252.52 9430,2135.4 9430,2071 J204.3@9481,2020
  Signal Layer 3 w20: 10550,4198.66 v1(10550,4220)
  Signal Layer 4 w20: 10550,4190 v1(10550,4220)
  Signal Layer 4 w50: J206.8@7530,4670 J206.6@7630,4670 7700,4740 7865.51,4740 7955.51,4650 7955.51,4468.37 8070,4353.88 9416.12,4353.88 9920,3850 9920,3763.15 C103.2@10210,3473.15
  Bottom Layer w20: 10550,4198.66 v1(10550,4220)
  other v1: 10450,30 10480,60 6100,100 9680,380 10420,380 9200,410 6090,440 7990,470 6130,480 9590,480 9580,760 10590,1490 9490,2390 9460,3320 9320,4010 9280,4050 9240,4090 10480,4110 10530,4110 10580,4110 10630,4110 10680,4110 10730,4110 9490,4120 9200,4130 9450,4160 7520,4170 7490,4200 9410,4200 9720,4210 9370,4240 9680,4250 9640,4290 9600,4330 9185,4670 9635,4670 10240,4693.46
VBATT: J101.1 J101.2 J101.3 J206.1 R237.2 XF103.1 XF103.2 | length 5021.2
  Top Layer w25: R237.2@10167.09,4270 v1(10230,4270)
  Signal Layer 1 w25: v1(10230,4270) 10230,4180 10980,3430 10980,3396.85 J101.3@11000,3376.85
  Signal Layer 2 w50: J206.1@7830,4570 7830,4430 7906.12,4353.88 9416.12,4353.88 9711.57,4058.43 10318.43,4058.43 J101.3@11000,3376.85
VBUS: J100.1 J100.2 XF100.1 XF100.2
VPRI_SENSE: R228.2 U209.1 U209.4 | length 357.2
  Top Layer w12: U209.4@4072.6,4316.53 U209.4@4072.6,4305.87 4116.73,4350 4129.84,4350 4147.4,4367.56 U209.1@4147.4,4414.13 4160,4426.73 R228.2@4160,4608.5
Vref0: J202.9 R206.2 | length 166.2
  Top Layer w12: J202.9@4297.99,5007.05 4297.99,5082.38 4305.61,5090 4305.61,5109.38 4310,5113.76 4310,5140 R206.2@4330,5160
VSEC_SENSE: C221.1 R209.2 R238.2 U206.1 | length 346.3
  Top Layer w20: R209.2@4305.91,4680.98 4318.5,4668.38 U206.1@4370.28,4668.38 v1(4370.28,4696.85) ; v1(4494.41,4630.98) 4518.03,4630.98 C221.1@4534.41,4614.6 R238.2@4584.41,4614.61
  Signal Layer 1 w20: v1(4370.28,4696.85) 4436.14,4630.98 v1(4494.41,4630.98)
VSEC_SENSE_2: J209.5 R226.2 | length 2130.8
  Top Layer w20: v1(4830,5010) R226.2@4878.5,5010
  Signal Layer 1 w25: v1(4830,5010) 5170,4670 6250,4670 v1(6320,4600)
  Signal Layer 3 w25: v1(6320,4600) 6350,4570 J209.5@6730,4570
pads on no net: H200.1 H201.1 H202.1 H203.1 H204.0 H205.0 H206.0 H207.0 J200.1 J201.1 J202.1 J202.2 J202.3 J202.4 J202.5 J202.6 J202.8 J202.11 J202.16 J202.17 J202.20 J202.26 J202.29 J202.30 J202.31 J202.32 J202.33 J202.36 J202.37 J202.39 J202.40 J202.41 J202.42 J202.43 J202.44 J202.45 J202.58 J202.59 J202.60 J202.62 J202.63 J202.64 J202.66 J202.67 J202.68 J202.69 J202.70 J202.71 J202.72 J202.73 J202.75 J202.77 J202.79 J202.80 J202.81 J202.82 J202.85 J202.86 J202.87 J202.88 J202.89 J202.90 J202.91 J202.92 J202.93 J202.94 J202.95 J202.96 J202.99 J202.100 J202.101 J202.102 J202.103 J202.104 J202.105 J202.106 J202.107 J202.108 J202.109 J202.110 J202.113 J202.114 J202.115 J202.116 J202.117 J202.118 J202.119 J202.120 J202.181 J202.182 J202.185 J202.186 J204.1 J204.2 J205.1 J205.2 J206.2 J206.3 J206.4 J206.5 J207.61 J207.62 J207.121 J207.122 J207.123 J207.124 J207.125 J207.126 J207.127 J207.128 J207.129 J207.130 J207.131 J207.132 J207.133 J207.134 J207.136 J207.137 J207.138 J207.139 J207.140 J207.141 J207.142 J207.143 J207.144 J207.145 J207.146 J207.147 J207.148 J207.149 J207.150 J207.151 J207.152 J207.153 J207.154 J207.155 J207.156 J207.159 J207.160 J207.161 J207.162 J207.163 J207.164 J207.165 J207.166 J207.167 J207.168 J207.169 J207.170 J207.171 J207.172 J207.173 J207.174 J207.175 J207.176 J207.177 J207.178 U202.4 U204.2 U204.6 U204.8 U204.10 U204.11 U204.15 U208.2 U208.6 U208.8 U208.10 U208.11 U208.15 U210.5 U211.5

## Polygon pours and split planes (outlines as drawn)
5Vp on Top Layer "5Vp" (solid, pour order 275): 3750,5790 3730,5770 3730,5531.65 3748.7,5512.95 5627.46,5512.96 6620.42,4520 6910,4520 6990,4600 6990,5010 6210,5790
5Vp on Top Layer "5Vp" (solid, pour order 274): 6190,5150 6820,4520 7060,4520 7090,4550 7090,5010 7460,5380 9710,5380 9770,5320 9770,5080 9790,5060 10050,5060 10160,5170 10160,5450 9820,5790 6190,5790
PGND on Top Layer "PGND" (solid, pour order 294): 1830,1910 2320,1420 2320,1090 2910,500 5710,500 5730,480 5730,30 5710,10 1610,10 1480,140 1480,1910
NetC100_1 on Top Layer "C100_1" (solid, pour order 239): 29 vertices, not listed, extent 8100,200 9310,1980
VBATT on Top Layer "VBATT" (solid, pour order 238): 11020,2230 11070,2280 11070,3440 11040,3470 10920,3470 10760,3310 10760,2280 10810,2230
NetC100_2 on Top Layer "C100_2" (solid, pour order 234): 8120,580 8100,600 8100,1120 8648.66,1120 8648.66,1190 8742.6,1190 8760,1172.6 8760,620 8720,580
RTN on Top Layer "RTN" (solid, pour order 231): 590,4070 570,4050 570,3650 730,3490 1570,3490 1590,3510 1590,3730 1250,4070
PGND on Top Layer "PGND" (solid, pour order 230): 1080,3430 1020,3370 1020,3340 1020,1560 1070,1510 1470,1510 1830,1870 1830,2850 1750,2930 1750,3370 1690,3430
NetC102_2 on Top Layer "C102_2" (solid, pour order 229): 1340,2900 1310,2870 1200,2870 1180,2850 1180,2400 1200,2380 1330,2380 1350,2360 1400,2360 1420,2380 1420,2880 1400,2900
NetC101_2 on Top Layer "C101_2" (solid, pour order 227): 1340,1350 1310,1320 1180,1320 1160,1300 1160,850 1180,830 1320,830 1340,810 1390,810 1410,830 1410,1340 1400,1350
CS on Top Layer "CS" (solid, pour order 224): 19 vertices, not listed, extent 1900,1640 2760,3290
NetC122_2 on Top Layer "C122_2" (solid, pour order 221): 24 vertices, not listed, extent 2640,2330 3010,3340
NetC122_1 on Top Layer "C122_1" (solid, pour order 220): 3090,3340 3070,3320 3070,2350 3090,2330 3550,2330 3600,2380 3600,3290 3550,3340
NetQ101_2 on Top Layer "Q101_2" (solid, pour order 219): 17 vertices, not listed, extent 2640,820 3630,1550
VBUS on Top Layer "VBUS" (solid, pour order 216): 620,3310 650,3340 860,3340 890,3310 890,2780 890,2320 860,2290 650,2290 620,2320
NetJ105_1 on Top Layer "J105_1" (solid, pour order 241): 19 vertices, not listed, extent 8100,2720 9320,4060
SGND on Top Layer "SGND" (solid, pour order 243): 40 vertices, not listed, extent 9200,360 11060,4210
BATT_RTN on Top Layer "BATT_RTN" (solid, pour order 244): 10320,4270 10300,4290 10300,4450 10410,4560 11170,4560 11190,4540 11190,3960 11170,3940 10961.89,3940 10810,4091.89 10810,4220 10760,4270
SGND on Top Layer "SGND" (solid, pour order 308): 6090,500 6070,480 6070,30 6090,10 6340,10 10480,10 10500,30 10500,390 10310,580 9560,580 9560,500
NetC100_2 on Bottom Layer "C100_2" (solid, pour order 334): 8120,580 8100,600 8100,1120 8648.66,1120 8648.66,1190 8742.6,1190 8760,1172.6 8760,620 8720,580
NetJ105_1 on Bottom Layer "J105_1" (solid, pour order 332): 19 vertices, not listed, extent 8100,2720 9320,4060
PGND on Bottom Layer "PGND" (solid, pour order 285): 1550,3210 1690,3210 1690,3080 1740,3030 1740,3020 1680,2960 1630,2960 1550,3040
PGND on Bottom Layer "PGND" (solid, pour order 284): 23 vertices, not listed, extent 510,2140 11190,5790
no net on Bottom Layer "C100_1" (solid, pour order 255): 29 vertices, not listed, extent 8100,200 9310,1980
no net on Bottom Layer "C100_1" (solid, pour order 254): 29 vertices, not listed, extent 8100,200 9310,1980
NetQ101_2 on Bottom Layer "Q101_2" (solid, pour order 248): 3300,1550 3190,1440 3190,1110 3300,1000 3520,1000 3630,1110 3630,1440 3520,1550
NetC100_1 on Bottom Layer "C100_1" (solid, pour order 240): 29 vertices, not listed, extent 8100,200 9310,1980
VBATT on Bottom Layer "VBATT" (solid, pour order 237): 11020,2230 11070,2280 11070,3440 11040,3470 10920,3470 10760,3310 10760,2280 10810,2230
NetC103_1 on Bottom Layer "C103_1" (solid, pour order 236): 9580,2360 9810,2130 9810,2560 9580,2790
NetC103_1 on Bottom Layer "C103_1" (solid, pour order 235): 41 vertices, not listed, extent 9190,190 11070,3940
RTN on Bottom Layer "RTN" (solid, pour order 232): 590,4070 570,4050 570,3650 730,3490 1570,3490 1590,3510 1590,3730 1250,4070
NetC102_2 on Bottom Layer "C102_2" (solid, pour order 228): 1340,2900 1310,2870 1200,2870 1180,2850 1180,2400 1200,2380 1330,2380 1350,2360 1400,2360 1420,2380 1420,2880 1400,2900
NetC101_2 on Bottom Layer "C101_2" (solid, pour order 226): 1340,1350 1310,1320 1180,1320 1160,1300 1160,850 1180,830 1320,830 1340,810 1390,810 1410,830 1410,1340 1400,1350
CS on Bottom Layer "CS" (solid, pour order 225): 19 vertices, not listed, extent 1900,1640 2760,3290
NetC122_1 on Bottom Layer "C122_1" (solid, pour order 223): 3090,3340 3070,3320 3070,2350 3090,2330 3550,2330 3600,2380 3600,3290 3550,3340
NetC122_2 on Bottom Layer "C122_2" (solid, pour order 222): 24 vertices, not listed, extent 2640,2330 3010,3340
HVBUS on Bottom Layer "HVBUS" (solid, pour order 218): 32 vertices, not listed, extent 650,140 3090,2280
VBUS on Bottom Layer "VBUS" (solid, pour order 217): 620,3310 650,3340 860,3340 890,3310 890,2780 890,2320 860,2290 650,2290 620,2320
BATT_RTN on Bottom Layer "BATT_RTN" (solid, pour order 245): 10320,4270 10300,4290 10300,4450 10410,4560 11170,4560 11190,4540 11190,3960 11170,3940 10961.89,3940 10810,4091.89 10810,4220 10760,4270
PGND on Bottom Layer "PGND" (solid, pour order 246): 1080,3430 1020,3370 1020,3340 1020,1560 1070,1510 1470,1510 1830,1870 1830,2850 1590,3090 1590,3410 1570,3430
SGND on Bottom Layer "SGND" (solid, pour order 298): 25 vertices, not listed, extent 9500,360 11060,4210
SGND on Bottom Layer "SGND" (solid, pour order 299): 20 vertices, not listed, extent 7460,1840 10400,4770
SGND on Bottom Layer "SGND" (solid, pour order 305): 6090,500 6070,480 6070,30 6090,10 6340,10 10480,10 10500,30 10500,390 10310,580 9560,580 9560,500
NetC100_2 on Signal Layer 4 "C100_2" (solid, pour order 336): 8120,580 8100,600 8100,1120 8648.66,1120 8648.66,1190 8742.6,1190 8760,1172.6 8760,620 8720,580
NetJ105_1 on Signal Layer 4 "J105_1" (solid, pour order 324): 19 vertices, not listed, extent 8100,2720 9320,4060
PGND on Signal Layer 4 "PGND" (solid, pour order 322): 22 vertices, not listed, extent 510,2140 11190,5790
PGND on Signal Layer 4 "PGND" (solid, pour order 316): 1830,1910 2320,1420 2320,1090 2910,500 5710,500 5730,480 5730,30 5710,10 1610,10 1480,140 1480,1910
SGND on Signal Layer 4 "SGND" (solid, pour order 312): 9740,3940 9850,3830 10000,3980 9900,4080 9880,4080
SGND on Signal Layer 4 "SGND" (solid, pour order 311): 17 vertices, not listed, extent 7460,3710 10400,4770
PGND on Signal Layer 4 "PGND" (solid, pour order 290): 1080,3430 1020,3370 1020,3340 1020,1560 1070,1510 1470,1510 1830,1870 1830,2850 1590,3090 1590,3410 1570,3430
BATT_RTN on Signal Layer 4 "BATT_RTN" (solid, pour order 282): 10320,4270 10300,4290 10300,4450 10410,4560 11170,4560 11190,4540 11190,3960 11170,3940 10961.89,3940 10810,4091.89 10810,4220 10760,4270
SGND on Signal Layer 4 "SGND" (solid, pour order 280): 39 vertices, not listed, extent 9200,360 11060,4210
VBATT on Signal Layer 4 "VBATT" (solid, pour order 273): 11020,2230 11070,2280 11070,3440 11040,3470 10920,3470 10760,3310 10760,2280 10810,2230
VBUS on Signal Layer 4 "VBUS" (solid, pour order 268): 620,3310 650,3340 860,3340 890,3310 890,2780 890,2320 860,2290 650,2290 620,2320
NetC100_1 on Signal Layer 4 "C100_1" (solid, pour order 262): 29 vertices, not listed, extent 8100,200 9310,1980
NetQ101_2 on Signal Layer 4 "Q101_2" (solid, pour order 249): 17 vertices, not listed, extent 2640,820 3630,1550
SGND on Signal Layer 4 "SGND" (solid, pour order 310): 6090,500 6070,480 6070,30 6090,10 6340,10 10480,10 10500,30 10500,390 10310,580 9560,580 9560,500
NetC100_2 on Signal Layer 2 "C100_2" (solid, pour order 338): 8120,580 8100,600 8100,1120 8648.66,1120 8648.66,1190 8742.6,1190 8760,1172.6 8760,620 8720,580
NetJ105_1 on Signal Layer 2 "J105_1" (solid, pour order 326): 19 vertices, not listed, extent 8100,2720 9320,4060
PGND on Signal Layer 2 "PGND" (solid, pour order 291): 1070,3420 1020,3370 1020,3340 1020,1560 1070,1510 1470,1510 1830,1870 1830,2850 1590,3090 1590,3370.87 1540.87,3420
VBATT on Signal Layer 2 "VBATT" (solid, pour order 277): 11020,2230 11070,2280 11070,3440 11040,3470 10920,3470 10760,3310 10760,2280 10810,2230
VBUS on Signal Layer 2 "VBUS" (solid, pour order 269): 620,3310 650,3340 860,3340 890,3310 890,2780 890,2320 860,2290 650,2290 620,2320
NetC100_1 on Signal Layer 2 "C100_1" (solid, pour order 257): 29 vertices, not listed, extent 8100,200 9310,1980
NetC103_1 on Signal Layer 2 "C103_1" (solid, pour order 253): 9600,2340 9810,2130 9810,2560 9600,2770
NetC103_1 on Signal Layer 2 "C103_1" (solid, pour order 252): 41 vertices, not listed, extent 9190,190 11070,3940
HVBUS on Signal Layer 2 "HVBUS" (solid, pour order 247): 30 vertices, not listed, extent 650,140 3090,2280
SGND on Signal Layer 2 "SGND" (solid, pour order 300): 25 vertices, not listed, extent 9500,360 11060,4210
SGND on Signal Layer 2 "SGND" (solid, pour order 301): 20 vertices, not listed, extent 7460,1840 10400,4770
